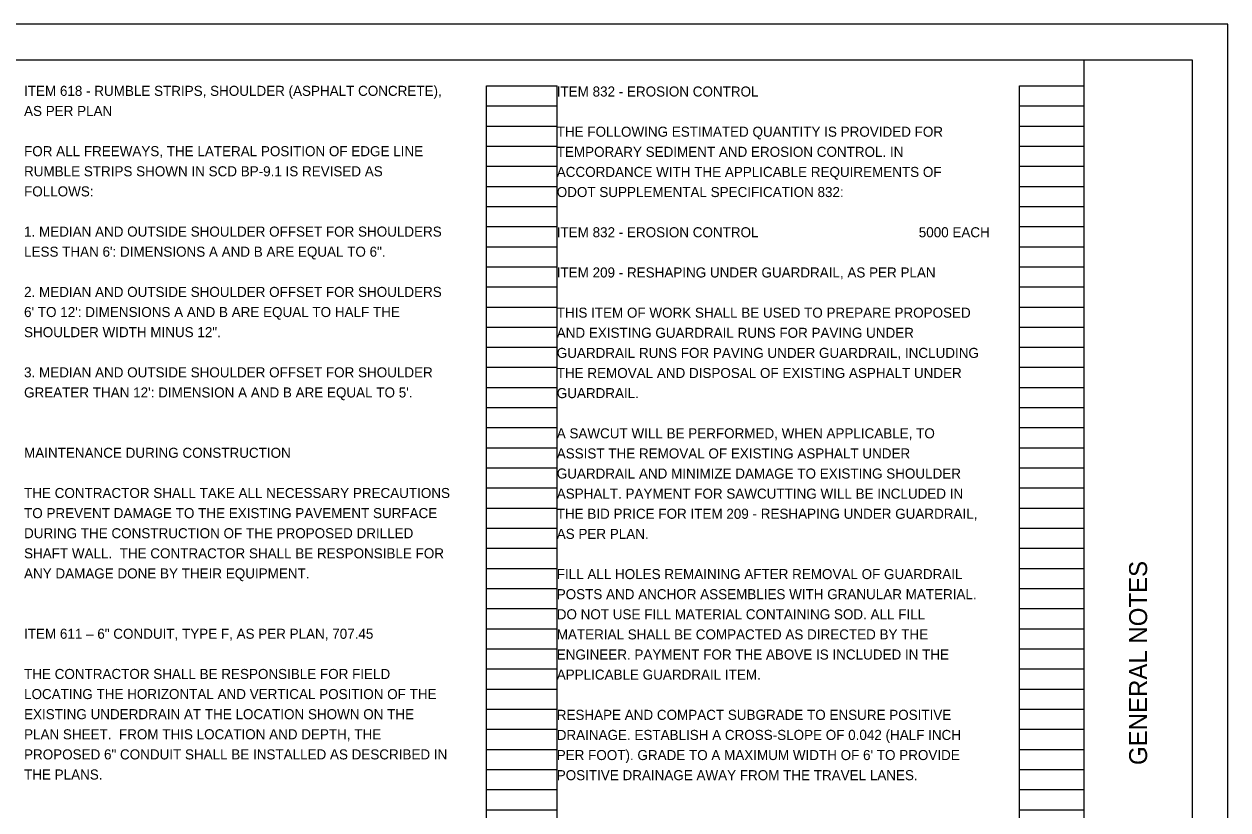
# Model space of a CAD drawing. Extents: x 0 to 34, y 0 to 22.
# Drawn here: x 17.24 to 34, y 11.06 to 22 of the extents above; entities that cross this region are included whole.
import ezdxf

# ---------------------------------------------------------------- set-up
doc = ezdxf.new("R2010")
doc.units = 0
for name, color, linetype in [('SH_Border', 7, 'Continuous'), ('SH_Cut_Line', 7, 'Continuous'), ('SH_Data', 7, 'Continuous'), ('SH_Text', 7, 'Continuous')]:
    doc.layers.add(name, color=color, linetype=linetype)

msp = doc.modelspace()

# ---------------------------------------------------------------- linework, layer by layer
at = {"layer": 'SH_Border'}
msp.add_line((32, 0.5), (32, 21.5), dxfattribs=at)
msp.add_lwpolyline([(1.5, 21.5), (33.5, 21.5), (33.5, 0.5), (1.5, 0.5)], close=True, dxfattribs=at)
at = {"layer": 'SH_Cut_Line'}
msp.add_lwpolyline([(0, 0), (34, 0), (34, 22), (0, 22)], close=True, dxfattribs=at)
at = {"layer": 'SH_Data'}
for p, q in [((23.68, 0.98), (23.68, 21.14)), ((23.68, 21.14), (24.66, 21.14)), ((24.66, 0.98), (24.66, 21.14)), ((31.1, 0.98), (31.1, 21.14)), ((31.1, 21.14), (32, 21.14)), ((32, 0.98), (32, 21.14)), ((23.68, 20.86), (24.66, 20.86)), ((31.1, 20.86), (32, 20.86)), ((23.68, 20.58), (24.66, 20.58)), ((31.1, 20.58), (32, 20.58)), ((23.68, 20.3), (24.66, 20.3)), ((31.1, 20.3), (32, 20.3)), ((23.68, 20.02), (24.66, 20.02)), ((31.1, 20.02), (32, 20.02)), ((23.68, 19.74), (24.66, 19.74)), ((31.1, 19.74), (32, 19.74)), ((23.68, 19.46), (24.66, 19.46)), ((31.1, 19.46), (32, 19.46)), ((23.68, 19.18), (24.66, 19.18)), ((31.1, 19.18), (32, 19.18)), ((23.68, 18.9), (24.66, 18.9)), ((31.1, 18.9), (32, 18.9)), ((23.68, 18.62), (24.66, 18.62)), ((31.1, 18.62), (32, 18.62)), ((23.68, 18.34), (24.66, 18.34)), ((31.1, 18.34), (32, 18.34)), ((23.68, 18.06), (24.66, 18.06)), ((31.1, 18.06), (32, 18.06)), ((23.68, 17.78), (24.66, 17.78)), ((31.1, 17.78), (32, 17.78)), ((23.68, 17.5), (24.66, 17.5)), ((31.1, 17.5), (32, 17.5)), ((23.68, 17.22), (24.66, 17.22)), ((31.1, 17.22), (32, 17.22)), ((23.68, 16.94), (24.66, 16.94)), ((31.1, 16.94), (32, 16.94)), ((23.68, 16.66), (24.66, 16.66)), ((31.1, 16.66), (32, 16.66)), ((23.68, 16.38), (24.66, 16.38)), ((31.1, 16.38), (32, 16.38)), ((23.68, 16.1), (24.66, 16.1)), ((31.1, 16.1), (32, 16.1)), ((23.68, 15.82), (24.66, 15.82)), ((31.1, 15.82), (32, 15.82)), ((23.68, 15.54), (24.66, 15.54)), ((31.1, 15.54), (32, 15.54)), ((23.68, 15.26), (24.66, 15.26)), ((31.1, 15.26), (32, 15.26)), ((23.68, 14.98), (24.66, 14.98)), ((31.1, 14.98), (32, 14.98)), ((23.68, 14.7), (24.66, 14.7)), ((31.1, 14.7), (32, 14.7)), ((23.68, 14.42), (24.66, 14.42)), ((31.1, 14.42), (32, 14.42)), ((23.68, 14.14), (24.66, 14.14)), ((31.1, 14.14), (32, 14.14)), ((23.68, 13.86), (24.66, 13.86)), ((31.1, 13.86), (32, 13.86)), ((23.68, 13.58), (24.66, 13.58)), ((31.1, 13.58), (32, 13.58)), ((23.68, 13.3), (24.66, 13.3)), ((31.1, 13.3), (32, 13.3)), ((23.68, 13.02), (24.66, 13.02)), ((31.1, 13.02), (32, 13.02)), ((23.68, 12.74), (24.66, 12.74)), ((31.1, 12.74), (32, 12.74)), ((23.68, 12.46), (24.66, 12.46)), ((31.1, 12.46), (32, 12.46)), ((23.68, 12.18), (24.66, 12.18)), ((31.1, 12.18), (32, 12.18)), ((23.68, 11.9), (24.66, 11.9)), ((31.1, 11.9), (32, 11.9)), ((23.68, 11.62), (24.66, 11.62)), ((31.1, 11.62), (32, 11.62)), ((23.68, 11.34), (24.66, 11.34)), ((31.1, 11.34), (32, 11.34)), ((23.68, 11.06), (24.66, 11.06)), ((31.1, 11.06), (32, 11.06))]:
    msp.add_line(p, q, dxfattribs=at)

# ---------------------------------------------------------------- texts
msp.add_text('GENERAL NOTES', height=0.25, rotation=90, dxfattribs=at).set_placement((32.875, 11.682))
at = {"layer": 'SH_Text'}
for s, p in [('ITEM 618 - RUMBLE STRIPS, SHOULDER (ASPHALT CONCRETE), ', (17.24, 21)), ('ITEM 832 - EROSION CONTROL', (24.656, 20.991)), ('AS PER PLAN', (17.24, 20.72)), ('THE FOLLOWING ESTIMATED QUANTITY IS PROVIDED FOR ', (24.656, 20.431)), ('FOR ALL FREEWAYS, THE LATERAL POSITION OF EDGE LINE ', (17.24, 20.16)), ('TEMPORARY SEDIMENT AND EROSION CONTROL. IN ', (24.656, 20.151)), ('RUMBLE STRIPS SHOWN IN SCD BP-9.1 IS REVISED AS ', (17.24, 19.88)), ('ACCORDANCE WITH THE APPLICABLE REQUIREMENTS OF ', (24.656, 19.871)), ('FOLLOWS:', (17.24, 19.6)), ('ODOT SUPPLEMENTAL SPECIFICATION 832:', (24.656, 19.591)), ('1. MEDIAN AND OUTSIDE SHOULDER OFFSET FOR SHOULDERS ', (17.24, 19.04)), ('ITEM 832 - EROSION CONTROL', (24.656, 19.031)), ('5000 EACH', (29.696, 19.031)), ('LESS THAN 6\': DIMENSIONS A AND B ARE EQUAL TO 6".', (17.24, 18.76)), ('ITEM 209 - RESHAPING UNDER GUARDRAIL, AS PER PLAN', (24.656, 18.471)), ('2. MEDIAN AND OUTSIDE SHOULDER OFFSET FOR SHOULDERS ', (17.24, 18.2)), ("6' TO 12': DIMENSIONS A AND B ARE EQUAL TO HALF THE ", (17.24, 17.92)), ('THIS ITEM OF WORK SHALL BE USED TO PREPARE PROPOSED ', (24.656, 17.911)), ('SHOULDER WIDTH MINUS 12".', (17.24, 17.64)), ('AND EXISTING GUARDRAIL RUNS FOR PAVING UNDER ', (24.656, 17.631)), ('GUARDRAIL RUNS FOR PAVING UNDER GUARDRAIL, INCLUDING ', (24.656, 17.351)), ('3. MEDIAN AND OUTSIDE SHOULDER OFFSET FOR SHOULDER ', (17.24, 17.08)), ('THE REMOVAL AND DISPOSAL OF EXISTING ASPHALT UNDER ', (24.656, 17.071)), ("GREATER THAN 12': DIMENSION A AND B ARE EQUAL TO 5'.", (17.24, 16.8)), ('GUARDRAIL.', (24.656, 16.791)), ('A SAWCUT WILL BE PERFORMED, WHEN APPLICABLE, TO ', (24.656, 16.231)), ('MAINTENANCE DURING CONSTRUCTION', (17.24, 15.96)), ('ASSIST THE REMOVAL OF EXISTING ASPHALT UNDER ', (24.656, 15.951)), ('GUARDRAIL AND MINIMIZE DAMAGE TO EXISTING SHOULDER ', (24.656, 15.671)), ('THE CONTRACTOR SHALL TAKE ALL NECESSARY PRECAUTIONS ', (17.24, 15.4)), ('ASPHALT. PAYMENT FOR SAWCUTTING WILL BE INCLUDED IN ', (24.656, 15.391)), ('TO PREVENT DAMAGE TO THE EXISTING PAVEMENT SURFACE ', (17.24, 15.12)), ('THE BID PRICE FOR ITEM 209 - RESHAPING UNDER GUARDRAIL, ', (24.656, 15.111)), ('DURING THE CONSTRUCTION OF THE PROPOSED DRILLED ', (17.24, 14.84)), ('AS PER PLAN.', (24.656, 14.831)), ('SHAFT WALL.  THE CONTRACTOR SHALL BE RESPONSIBLE FOR ', (17.24, 14.56)), ('ANY DAMAGE DONE BY THEIR EQUIPMENT.', (17.24, 14.28)), ('FILL ALL HOLES REMAINING AFTER REMOVAL OF GUARDRAIL ', (24.656, 14.271)), ('POSTS AND ANCHOR ASSEMBLIES WITH GRANULAR MATERIAL.  ', (24.656, 13.991)), ('DO NOT USE FILL MATERIAL CONTAINING SOD. ALL FILL ', (24.656, 13.711)), ('ITEM 611 – 6" CONDUIT, TYPE F, AS PER PLAN, 707.45', (17.24, 13.44)), ('MATERIAL SHALL BE COMPACTED AS DIRECTED BY THE ', (24.656, 13.431)), ('ENGINEER. PAYMENT FOR THE ABOVE IS INCLUDED IN THE ', (24.656, 13.151)), ('THE CONTRACTOR SHALL BE RESPONSIBLE FOR FIELD ', (17.24, 12.88)), ('APPLICABLE GUARDRAIL ITEM.', (24.656, 12.871)), ('LOCATING THE HORIZONTAL AND VERTICAL POSITION OF THE ', (17.24, 12.6)), ('EXISTING UNDERDRAIN AT THE LOCATION SHOWN ON THE ', (17.24, 12.32)), ('RESHAPE AND COMPACT SUBGRADE TO ENSURE POSITIVE ', (24.656, 12.311)), ('PLAN SHEET.  FROM THIS LOCATION AND DEPTH, THE ', (17.24, 12.04)), ('DRAINAGE. ESTABLISH A CROSS-SLOPE OF 0.042 (HALF INCH ', (24.656, 12.031)), ('PROPOSED 6" CONDUIT SHALL BE INSTALLED AS DESCRIBED IN ', (17.24, 11.76)), ("PER FOOT). GRADE TO A MAXIMUM WIDTH OF 6' TO PROVIDE ", (24.656, 11.751)), ('THE PLANS.', (17.24, 11.48)), ('POSITIVE DRAINAGE AWAY FROM THE TRAVEL LANES. ', (24.656, 11.471))]:
    msp.add_text(s, height=0.14, dxfattribs=at).set_placement(p)

doc.saveas('drawing.dxf')
